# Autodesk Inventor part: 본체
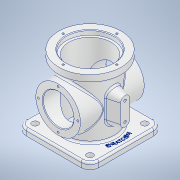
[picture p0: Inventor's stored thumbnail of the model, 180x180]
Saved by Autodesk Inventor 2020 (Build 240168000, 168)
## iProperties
Created: 2021-03
Part Number: 본체
Material: 알루미늄 6061
Document SubType Name: Modeling
Designer: USER
Mass: 869.331 g
Surface Area: 881.277 cm^2
Volume: 321.975 cm^3
Density: 2.7 g/cm^3
Appearance: 알루미늄 - 평지
Author: USER
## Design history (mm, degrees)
sketch "스케치1"
  geometry: L1 (-57, 57)-(57, 57); L2 (57, 57)-(57, -57); L3 (57, -57)-(-57, -57); L4 (-57, -57)-(-57, 57); L5 (-57, 57)-(57, -57); L6 (57, 57)-(-57, -57); 1 further point
  constraints: 12 end point, 2 midpoint, 2 parallel, 2 perpendicular, 1 horizontal
  dimensions: "d0" = 114 distance of L2.end L3.end
extrude "돌출1" new body sketch "스케치1" distance "d1" = 10; taper "d2" = 0 deg
sketch "스케치2"
  geometry: C1 r 38 at (0, 0); 1 further point
  constraints: 1 centre point, 1 coincident
  dimensions: "d3" = 76 diameter of C1
extrude "돌출2" join sketch "스케치2" distance "d4" = 88; taper "d5" = 0 deg
sketch "스케치3"
  geometry: C1 r 49 at (0, 0); 1 further point
  constraints: 1 centre point, 1 coincident
  dimensions: "d6" = 98 diameter of C1
extrude "돌출3" join sketch "스케치3" distance "d7" = 13; taper "d8" = 0 deg
sketch "스케치4"
  geometry: L1 (57, 0)-(-57, 0) reference; C1 r 35 at (0, 54); 1 further point
  constraints: 1 centre point, 1 vertical alignment
  dimensions: "d9" = 70 diameter of C1; "d10" = 54 distance from line of L1 C1.centre
extrude "돌출4" join sketch "스케치4" stored distance "d11" = 100; taper "d12" = 0 deg
sketch "스케치5"
  geometry: C1 r 37 at (0, 0); 1 further point
  constraints: 1 centre point, 1 coincident
  dimensions: "d13" = 74 diameter of C1
extrude "돌출5" cut sketch "스케치5" distance "d14" = 7; taper "d15" = 0 deg
sketch "스케치6"
  geometry: C1 r 33 at (0, 0); 1 further point
  constraints: 1 centre point, 1 coincident
  dimensions: "d16" = 66 diameter of C1
extrude "돌출6" cut sketch "스케치6" extent not by distance; stored distance "d17" = 7; taper "d18" = 0 deg
sketch "스케치8"
  geometry: C1 r 35 at (0, 0) reference; C2 r 24 at (0, 0); 1 further point
  constraints: 1 centre point, 1 coincident
  dimensions: "d19" = 48 diameter of C2
extrude "돌출7" cut sketch "스케치8" extent not by distance; stored distance "d20" = 0; taper "d21" = 0 deg
sketch "스케치9"
  geometry: L1 (24, 22.65)-(24, 50) reference; C1 r 37 at (0, 0) reference; C2 r 49 at (0, 0) reference; 2 further points
  constraints: 1 vertical alignment
  dimensions: "d22" = 42 distance of point (0, 0) point (0, 42)
hole "구멍1" sketch "스케치9" at (0, 42) diameter "d23" = 3.242; stored, may be unused: countersink angle "d27" = 90 deg, drill point angle "d29" = 118 deg; dims "d24" = 6, "d25" = 4, "d26" = 2, "d28" = 8
sketch "스케치10"
  geometry: C1 r 24 at (0, 0) reference; C2 r 35 at (0, 0) reference; 2 further points
  constraints: 1 vertical alignment
  dimensions: "d33" = 31 distance of C1.centre point (0, 31)
hole "구멍2" sketch "스케치10" at (0, 31) diameter "d34" = 3.242; stored, may be unused: countersink angle "d38" = 90 deg, drill point angle "d40" = 118 deg; dims "d35" = 6, "d36" = 4, "d37" = 2, "d39" = 8
node "작업 평면1"
sketch "스케치11"
  geometry: L1 (68.5, 0)-(39.5, 0); L2 (68.5, 7)-(39.5, 7); L3 (39.5, -7)-(68.5, -7); L4 (0, 57)-(0, -57) reference; A1 r 7 centre (68.5, 0) between (68.5, -7) and (68.5, 7); A2 r 7 centre (39.5, 0) between (39.5, 7) and (39.5, -7); 3 further points
  constraints: 8 end point, 4 point on circle, 4 tangent, 2 centre point, 2 midpoint, 1 horizontal, 1 horizontal alignment, 1 parallel
  dimensions: "d45" = 14 distance between parallel lines of L3 L2; "d46" = 29 distance of L1.end L1.start; "d47" = 54 distance from line of L4 point (54, 0)
extrude "돌출8" join sketch "스케치11" stored distance "d48" = 7; taper "d49" = 15 deg
sketch "스케치12"
  geometry: L1 (57, 57)-(-57, 57) reference; L2 (57, -57)-(57, 57) reference; C1 r 5 at (43, 43); 1 further point
  constraints: 1 centre point
  dimensions: "d50" = 10 diameter of C1; "d51" = 14 distance from line of L1 C1.centre; "d52" = 14 distance from line of L2 C1.centre
extrude "돌출9" cut sketch "스케치12" extent not by distance; stored distance "d53" = 0; taper "d54" = 0 deg
fillet "모깎기1" dims "d55" = 14
fillet "모깎기2" dims "d56" = 3
fillet "모깎기3" dims "d57" = 3
fillet "모깎기4" dims "d58" = 3
fillet "모깎기5" dims "d59" = 3
fillet "모깎기6" dims "d60" = 3
fillet "모깎기7" dims "d61" = 3
chamfer "모따기1" distance "d62" = 1; stored, may be unused: second distance "d63" = 2, angle "d64" = 45 deg
chamfer "모따기2" distance "d65" = 1; stored, may be unused: second distance "d66" = 2, angle "d67" = 45 deg
chamfer "모따기3" distance "d68" = 1; stored, may be unused: second distance "d69" = 2, angle "d70" = 45 deg
sketch "스케치13"
  geometry: L1 (-7, 68.5)-(-7, 39.5) reference; L2 (7, 39.5)-(7, 68.5) reference; A1 r 7 centre (0, 39.5) between (-7, 39.5) and (7, 39.5) reference; A2 r 7 centre (0, 68.5) between (7, 68.5) and (-7, 68.5) reference; 3 further points
  constraints: 2 coincident
hole "구멍3" sketch "스케치13" at (0, 68.5), (0, 39.5) diameter "d71" = 4.134; stored, may be unused: countersink angle "d75" = 90 deg, drill point angle "d77" = 118 deg; dims "d72" = 8, "d73" = 4, "d74" = 2, "d76" = 10
sketch "스케치14"
  geometry: C1 r 50 at (0, 0); 1 further point
  constraints: 1 centre point, 1 coincident, 1 other
  dimensions: "d78" = 100 diameter of C1
feature "엠보싱1" sketch "스케치14" dims "d79" = 0.5, "d80" = 0
node "솔리드1"
pattern_circular "원형 패턴1" dims angle "d31" = 360 deg
pattern_circular "원형 패턴2" dims angle "d42" = 360 deg
mirror "미러1"
mirror "미러3"
mirror "미러4"
mirror "미러5"
node "투영된 루프1"
node "투영된 루프2"
node "투영된 루프3"
node "투영된 루프4"
feature "A9D066F2-1C7D-4E18-AEED-F7BC21143FA4" dims "d34" = 3.242, "d35" = 6, "d36" = 4, "d37" = 2, "d38" = 90 deg, "d39" = 8, "d40" = 118 deg
other parameters: "d44" = 55
